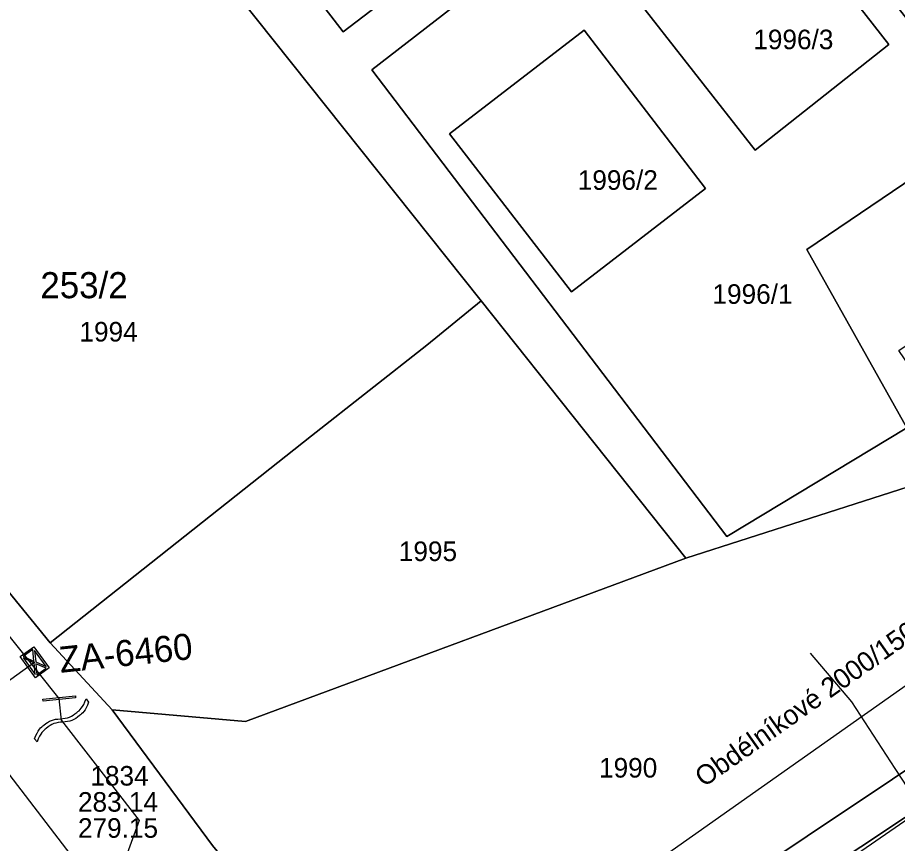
# Model space of a CAD drawing. Extents: x -570698 to -570232, y -1086952 to -1086596.
# Drawn here: x -570431.1 to -570363.7, y -1086738.4 to -1086675.1 of the extents above; entities that cross this region are included whole.
import ezdxf

# ---------------------------------------------------------------- set-up
doc = ezdxf.new("R2010")
doc.units = 0
for name, color, linetype in [('Adresní místo-text', 7, 'Continuous'), ('Armatura - popis', 7, 'Continuous'), ('Armatura vodovodní', 7, 'Continuous'), ('Default', 7, 'Continuous'), ('Dešťová vpusť', 7, 'Continuous'), ('Kanalizační přípojka', 7, 'Continuous'), ('Kanalizační stoka', 7, 'Continuous'), ('Parcela-polygon', 7, 'Continuous'), ('Parcela-text', 7, 'Continuous'), ('Popis kmenové stoky', 7, 'Continuous'), ('Popis šachty', 7, 'Continuous'), ('Vodovodní řad', 7, 'Continuous'), ('Změna stáří vedení', 7, 'Continuous')]:
    doc.layers.add(name, color=color, linetype=linetype)

msp = doc.modelspace()

# ---------------------------------------------------------------- linework, layer by layer
at = {"layer": 'Armatura vodovodní'}
msp.add_lwpolyline([(-570429.204, -1086727.358), (-570426.718, -1086727.096), (-570426.702, -1086727.252), (-570429.188, -1086727.514), (-570429.204, -1086727.358)], dxfattribs=at)
at = {"layer": 'Default'}
for points in [[(-570429.849, -1086730.393), (-570429.592, -1086729.7), (-570429.097, -1086729.318), (-570428.603, -1086728.935), (-570427.87, -1086728.862), (-570427.136, -1086728.788), (-570426.644, -1086728.407), (-570426.15, -1086728.025), (-570425.894, -1086727.334)], [(-570425.703, -1086727.581), (-570425.956, -1086728.271), (-570426.451, -1086728.653), (-570426.945, -1086729.036), (-570427.68, -1086729.111), (-570428.412, -1086729.183), (-570428.906, -1086729.565), (-570429.4, -1086729.948), (-570429.658, -1086730.64)]]:
    msp.add_open_spline(points, degree=3, dxfattribs=at)
at = {"layer": 'Dešťová vpusť'}
for points in [[(-570430.942, -1086724.095), (-570429.897, -1086723.343), (-570428.729, -1086724.966), (-570429.773, -1086725.718), (-570430.942, -1086724.095)], [(-570429.894, -1086724.44), (-570429.976, -1086723.555), (-570430.709, -1086724.082), (-570429.894, -1086724.44)], [(-570429.763, -1086724.499), (-570428.968, -1086724.848), (-570429.842, -1086723.633), (-570429.763, -1086724.499)], [(-570429.881, -1086724.584), (-570430.693, -1086724.226), (-570429.8, -1086725.467), (-570429.881, -1086724.584)], [(-570429.673, -1086725.49), (-570428.97, -1086724.984), (-570429.75, -1086724.641), (-570429.673, -1086725.49)]]:
    msp.add_lwpolyline(points, dxfattribs=at)
at = {"layer": 'Kanalizační přípojka'}
for points in [[(-570370.42, -1086723.84), (-570367.27, -1086727.57), (-570363.927, -1086732.684), (-570360.585, -1086737.798)], [(-570429.836, -1086724.531), (-570435.36, -1086728.507)]]:
    msp.add_lwpolyline(points, dxfattribs=at)
at = {"layer": 'Kanalizační stoka'}
for points in [[(-570416.01, -1086763.66), (-570340, -1086709.998), (-570334.265, -1086707.341), (-570324.416, -1086704.737), (-570313.599, -1086705.638), (-570281.39, -1086717.12)], [(-570451.361, -1086707.608), (-570438.76, -1086724.066), (-570426.16, -1086740.524)]]:
    msp.add_lwpolyline(points, dxfattribs=at)
at = {"layer": 'Parcela-polygon'}
for points in [[(-570417.92, -1086660.96), (-570406.2, -1086676.21), (-570386, -1086660.75), (-570383.74, -1086658.67), (-570393.72, -1086645.63), (-570397.14, -1086648.22), (-570396.25, -1086649.37), (-570387.14, -1086661.45), (-570392.47, -1086665.54), (-570401.63, -1086653.46), (-570401.73, -1086653.52), (-570404.26, -1086650.23)], [(-570453.79, -1086651.76), (-570467.38, -1086662.7), (-570451.08, -1086682.93), (-570445.98, -1086678.82), (-570434.1, -1086693.53), (-570433.05, -1086694.85), (-570438.47, -1086698.99), (-570437.38, -1086700.18), (-570443.07, -1086704.77), (-570443.22, -1086704.89), (-570435.57, -1086714.25), (-570435.72, -1086714.37), (-570428.66, -1086723.04), (-570408.62, -1086707.18), (-570399.8, -1086700.21), (-570395.64, -1086696.83), (-570424.7, -1086660.31), (-570438.26, -1086671.07), (-570442.64, -1086665.62)], [(-570363.02, -1086706.55), (-570370.68, -1086692.89), (-570356.68, -1086683.4), (-570376.49, -1086657.78), (-570404.01, -1086679.1), (-570376.81, -1086714.9)], [(-570384.09, -1086673.17), (-570373.72, -1086665.22), (-570364.4, -1086677.17), (-570374.63, -1086685.27)], [(-570364.4, -1086677.17), (-570373.72, -1086665.22), (-570384.09, -1086673.17), (-570374.63, -1086685.27)], [(-570355.38, -1086713.04), (-570360.77, -1086704.95), (-570361.85, -1086703.26), (-570363.62, -1086700.62), (-570359.23, -1086697.68), (-570337.92, -1086683.56), (-570337.62, -1086683.47), (-570329.26, -1086680.9), (-570336.7, -1086669.87), (-570356.68, -1086683.4), (-570370.68, -1086692.89), (-570363.02, -1086706.55), (-570360.86, -1086710.41), (-570356.5, -1086716.77), (-570329.42, -1086698.72), (-570330.83, -1086696.57)], [(-570398.06, -1086684.02), (-570387.75, -1086676.06), (-570378.44, -1086688.2), (-570388.71, -1086696.13)], [(-570378.44, -1086688.2), (-570387.75, -1086676.06), (-570398.06, -1086684.02), (-570388.71, -1086696.13)], [(-570396.95, -1086758.9), (-570302.37, -1086696.04), (-570307.04, -1086695.8), (-570320.65, -1086704.75), (-570323.72, -1086706.78), (-570351.03, -1086724.75), (-570396.74, -1086755.3), (-570401.48, -1086758.74), (-570401.33, -1086758.86), (-570399.38, -1086759.31)], [(-570399.8, -1086700.21), (-570408.62, -1086707.18), (-570428.66, -1086723.04), (-570423.89, -1086728.17), (-570413.68, -1086729.07), (-570379.95, -1086716.54), (-570395.64, -1086696.83)], [(-570351.03, -1086724.75), (-570356.5, -1086716.77), (-570360.86, -1086710.41), (-570379.95, -1086716.54), (-570413.68, -1086729.07), (-570423.89, -1086728.17), (-570416.22, -1086738.58), (-570401.54, -1086756.4), (-570400.84, -1086756.79), (-570396.74, -1086755.3)]]:
    msp.add_lwpolyline(points, close=True, dxfattribs=at)
for points in [[(-570424.7, -1086660.31), (-570395.64, -1086696.83), (-570379.95, -1086716.54), (-570360.86, -1086710.41), (-570363.02, -1086706.55), (-570376.81, -1086714.9), (-570404.01, -1086679.1), (-570376.49, -1086657.78), (-570356.68, -1086683.4), (-570336.7, -1086669.87)], [(-570386, -1086660.75), (-570406.2, -1086676.21), (-570417.92, -1086660.96)], [(-570291.64, -1086688.892), (-570302.37, -1086696.04), (-570396.95, -1086758.9), (-570417.85, -1086767.9), (-570426.99, -1086775.07), (-570430.55, -1086777.63), (-570432.81, -1086779.33), (-570437.1, -1086782.56), (-570450.62, -1086793.64), (-570452.87, -1086797.51), (-570456.3, -1086803.42), (-570469.27, -1086814.47), (-570499.22, -1086840.17), (-570503.94, -1086844.12), (-570508.33, -1086847.72), (-570512.7, -1086850.77), (-570519.4, -1086855.31), (-570522.96, -1086857.62), (-570528.66, -1086861.02), (-570535.32, -1086864.67), (-570544.494, -1086869.551)], [(-570432.81, -1086779.33), (-570430.55, -1086777.63), (-570426.99, -1086775.07), (-570417.85, -1086767.9), (-570396.95, -1086758.9), (-570399.38, -1086759.31), (-570401.33, -1086758.86), (-570401.48, -1086758.74), (-570396.74, -1086755.3), (-570400.84, -1086756.79), (-570401.54, -1086756.4), (-570416.22, -1086738.58), (-570423.89, -1086728.17), (-570428.66, -1086723.04), (-570435.72, -1086714.37)]]:
    msp.add_lwpolyline(points, dxfattribs=at)
at = {"layer": 'Vodovodní řad'}
for points in [[(-570427.776, -1086728.987), (-570427.953, -1086727.305), (-570440.565, -1086711.551), (-570453.177, -1086695.796), (-570476.544, -1086666.712), (-570505.845, -1086629.165), (-570508.799, -1086625.378)], [(-570292.345, -1086688.058), (-570314.222, -1086702.909), (-570395.154, -1086758.795)], [(-570427.776, -1086728.987), (-570421.845, -1086736.653), (-570427.901, -1086753.377)]]:
    msp.add_lwpolyline(points, dxfattribs=at)
at = {"layer": 'Změna stáří vedení'}
for points in [[(-570425.894, -1086727.334), (-570425.703, -1086727.581)], [(-570429.658, -1086730.64), (-570429.849, -1086730.393)]]:
    msp.add_lwpolyline(points, dxfattribs=at)

# ---------------------------------------------------------------- texts
at = {"layer": 'Adresní místo-text'}
msp.add_text('253/2', height=2, dxfattribs=at).set_placement((-570429.405, -1086696.62))
at = {"layer": 'Armatura - popis'}
msp.add_text('ZA-6460', height=2, rotation=6.00723, dxfattribs=at).set_placement((-570427.86, -1086725.345))
at = {"layer": 'Parcela-text'}
for s, p in [('1996/3', (-570374.78, -1086677.53)), ('1996/2', (-570388.23, -1086688.31)), ('1996/1', (-570377.91, -1086697.05)), ('1994', (-570426.41, -1086699.94)), ('1995', (-570401.94, -1086716.77)), ('1990', (-570386.6, -1086733.37))]:
    msp.add_text(s, height=1.5, dxfattribs=at).set_placement(p)
at = {"layer": 'Popis kmenové stoky'}
msp.add_text('Obdélníkové 2000/1500 TB', height=1.5, rotation=35.22155, dxfattribs=at).set_placement((-570378.57, -1086734.15))
at = {"layer": 'Popis šachty'}
for s, p in [('1834', (-570425.573, -1086733.985)), ('283.14', (-570426.523, -1086735.985)), ('279.15', (-570426.523, -1086737.985))]:
    msp.add_text(s, height=1.5, dxfattribs=at).set_placement(p)

doc.saveas('drawing.dxf')
